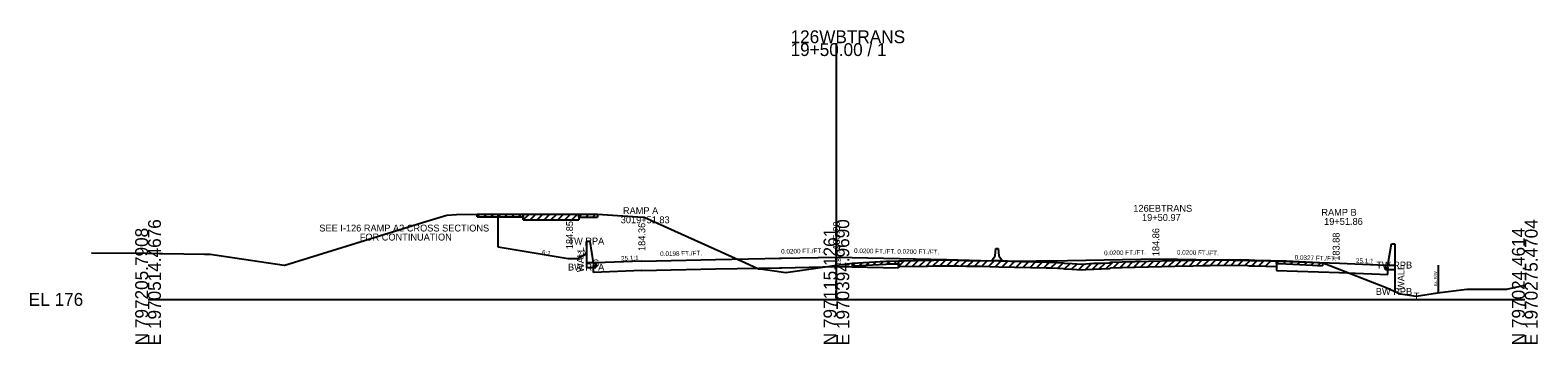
# Model space of a CAD drawing. Extents: x -6494 to 1970605, y -10 to 798140.
# Drawn here: x 974.3 to 1302.8, y 1990.3 to 2058.7 of the extents above; entities that cross this region are included whole.
import ezdxf

# ---------------------------------------------------------------- set-up
doc = ezdxf.new("R2010")
doc.units = 0
for name, color, linetype in [('Default', 7, 'Continuous'), ('RD_EX_SU_Misc_TxCode', 7, 'Continuous'), ('RD_GPK_XS_Cell', 7, 'Continuous'), ('RD_Sketch1', 7, 'Continuous'), ('RD_XS_Base', 7, 'Continuous'), ('RD_XS_Box', 7, 'Continuous'), ('RD_XS_EwShp', 7, 'Continuous'), ('RD_XS_ExGround', 7, 'Continuous'), ('RD_XS_ExPaveRet', 7, 'Continuous'), ('RD_XS_ExRW', 7, 'Continuous'), ('RD_XS_MedBWall', 7, 'Continuous'), ('RD_XS_Misc_Line', 7, 'Continuous'), ('RD_XS_Pave', 7, 'Continuous'), ('RD_XS_PaveOvlay', 7, 'Continuous'), ('RD_XS_PaveShd', 7, 'Continuous'), ('RD_XS_TieSlope', 7, 'Continuous'), ('RD_XS_TX_Elev_EX', 7, 'Continuous'), ('RD_XS_TX_Elev_PR', 7, 'Continuous'), ('RD_XS_TX_Misc', 7, 'Continuous'), ('RD_XS_TX_Notes', 7, 'Continuous'), ('RD_XS_TX_Profile', 7, 'Continuous'), ('RD_XS_TX_Slope', 7, 'Continuous'), ('RD_XS_TX_Station', 7, 'Continuous')]:
    doc.layers.add(name, color=color, linetype=linetype)

msp = doc.modelspace()

# ---------------------------------------------------------------- linework, layer by layer
at = {"layer": 'Default'}
for p, q in [((1184.58, 2009.5), (1184.75, 2011.08)), ((1184.75, 2011.08), (1185.25, 2011.08)), ((1185.25, 2011.08), (1185.42, 2009.5)), ((1184, 2008.67), (1184.58, 2009.5)), ((1184, 2008.42), (1184, 2008.67)), ((1186, 2008.42), (1184, 2008.42)), ((1185.42, 2009.5), (1186, 2008.67)), ((1186, 2008.67), (1186, 2008.42))]:
    msp.add_line(p, q, dxfattribs=at)
at = {"layer": 'RD_GPK_XS_Cell'}
for p, q in [((1150, 2000), (1150, 2055.87)), ((1000, 2000), (1150, 2000)), ((1150, 2000), (1300, 2000))]:
    msp.add_line(p, q, dxfattribs=at)
at = {"layer": 'RD_XS_Base'}
for p, q in [((1097.06, 2007.38), (1097.56, 2007.4)), ((1097.06, 2005.9), (1097.06, 2007.38)), ((1097.56, 2007.4), (1097.56, 2007.96)), ((1269.67, 2006.92), (1269.67, 2007.48)), ((1107.59, 2006.32), (1097.06, 2005.9)), ((1107.59, 2006.32), (1123.63, 2006.64)), ((1123.63, 2006.64), (1137.79, 2006.92)), ((1137.59, 2006.92), (1138, 2006.92)), ((1138, 2006.92), (1150, 2007.16)), ((1150, 2007.16), (1163.49, 2006.89)), ((1245.9, 2006.3), (1259.63, 2005.84)), ((1259.63, 2005.84), (1270.17, 2005.42)), ((1270.17, 2006.9), (1269.67, 2006.92)), ((1270.17, 2005.42), (1270.17, 2006.9))]:
    msp.add_line(p, q, dxfattribs=at)
at = {"layer": 'RD_XS_Box'}
for p, q in [((1095.56, 2011.8), (1095.56, 2007.96)), ((1097.56, 2007.96), (1095.56, 2007.96)), ((1269.67, 2007.48), (1271.68, 2007.48)), ((1271.68, 2007.48), (1271.68, 2001.74))]:
    msp.add_line(p, q, dxfattribs=at)
at = {"layer": 'RD_XS_ExGround'}
msp.add_line((987.67, 2010.15), (1000, 2010.05), dxfattribs=at)
msp.add_lwpolyline([(1000, 2010.05), (1002.48, 2010.03), (1003.14, 2010.03), (1007.8, 2009.94), (1012.29, 2009.86), (1013.51, 2009.84), (1029.68, 2007.49), (1029.83, 2007.48), (1060.74, 2017.07), (1065.09, 2018.4), (1067.21, 2018.48), (1071.69, 2018.62), (1074.17, 2018.62), (1077.48, 2018.62), (1084.94, 2018.6), (1094.44, 2018.59), (1096.53, 2018.58), (1097.91, 2018.57), (1107.79, 2017.95), (1108.09, 2017.93), (1130.07, 2008.04), (1133.01, 2006.7), (1133.93, 2006.58), (1135.5, 2006.36), (1138.95, 2005.88), (1147.07, 2007.04), (1150, 2007.44), (1153.49, 2007.91), (1160.76, 2008.34), (1161.26, 2008.37), (1161.76, 2008.37), (1169.83, 2008.53), (1171.19, 2008.55), (1173.61, 2008.6), (1176.58, 2008.55), (1178.37, 2008.52), (1181.39, 2008.47), (1185.4, 2008.39), (1195.68, 2008.15), (1196.93, 2008.12), (1199.43, 2008), (1199.7, 2007.9), (1201.33, 2007.81), (1203.39, 2007.68), (1204.36, 2007.77), (1206.07, 2007.88), (1207.66, 2007.92), (1209.56, 2008.01), (1209.76, 2008.13), (1212.23, 2008.22), (1223.73, 2008.5), (1227.76, 2008.59), (1229.72, 2008.62), (1231.43, 2008.66), (1235.71, 2008.72), (1239.58, 2008.61), (1239.91, 2008.6), (1241.2, 2008.56), (1247.97, 2008.39), (1253.72, 2008.09), (1255.9, 2007.97), (1257.51, 2007.38), (1269.79, 2002.57), (1272.81, 2001.23), (1273.93, 2001.08), (1276.36, 2000.71), (1280.98, 2001.45), (1287.37, 2002.21), (1294.36, 2002.27), (1296.07, 2002.25), (1299.67, 2003.06), (1300, 2003.14)], dxfattribs=at)
at = {"layer": 'RD_XS_ExPaveRet'}
for p, q in [((1071.69, 2017.99), (1071.69, 2018.62)), ((1071.69, 2017.99), (1074.17, 2018)), ((1074.17, 2018), (1077.48, 2018)), ((1077.48, 2018), (1081.75, 2017.98)), ((1081.75, 2017.36), (1081.75, 2018.61)), ((1081.75, 2018.61), (1081.75, 2017.98)), ((1081.75, 2017.36), (1084.94, 2017.35)), ((1084.94, 2017.35), (1093.89, 2017.34)), ((1093.89, 2018.59), (1093.89, 2017.34)), ((1093.89, 2017.96), (1093.89, 2018.59)), ((1093.89, 2017.96), (1094.44, 2017.96)), ((1094.44, 2017.96), (1096.53, 2017.95)), ((1096.53, 2017.95), (1097.91, 2017.95)), ((1097.91, 2018.57), (1097.91, 2017.95)), ((1153.49, 2007.29), (1153.49, 2007.91)), ((1153.49, 2007.29), (1160.76, 2007.71)), ((1160.76, 2007.71), (1161.26, 2007.74)), ((1161.26, 2007.74), (1161.76, 2007.75)), ((1161.76, 2007.75), (1163.49, 2007.78)), ((1163.49, 2007.16), (1163.49, 2008.41)), ((1163.49, 2008.41), (1163.49, 2007.78)), ((1171.19, 2007.3), (1173.61, 2007.35)), ((1173.61, 2007.35), (1176.58, 2007.3)), ((1223.73, 2007.25), (1227.76, 2007.34)), ((1227.76, 2007.34), (1229.72, 2007.37)), ((1229.72, 2007.37), (1231.43, 2007.41)), ((1231.43, 2007.41), (1235.71, 2007.47)), ((1235.71, 2007.47), (1239.58, 2007.36)), ((1239.58, 2007.36), (1239.91, 2007.35)), ((1239.91, 2007.35), (1241.2, 2007.31)), ((1245.9, 2008.44), (1245.9, 2007.19)), ((1245.9, 2007.82), (1245.9, 2008.44)), ((1245.9, 2007.82), (1247.97, 2007.76)), ((1247.97, 2007.76), (1253.72, 2007.46)), ((1253.72, 2007.46), (1255.9, 2007.35)), ((1255.9, 2007.97), (1255.9, 2007.35)), ((1163.49, 2007.16), (1169.83, 2007.28)), ((1169.83, 2007.28), (1171.19, 2007.3)), ((1176.58, 2007.3), (1178.37, 2007.27)), ((1178.37, 2007.27), (1181.39, 2007.22)), ((1181.39, 2007.22), (1185.4, 2007.14)), ((1185.4, 2007.14), (1195.68, 2006.9)), ((1195.68, 2006.9), (1196.93, 2006.87)), ((1196.93, 2006.87), (1199.43, 2006.75)), ((1199.43, 2006.75), (1199.7, 2006.65)), ((1199.7, 2006.65), (1201.33, 2006.56)), ((1201.33, 2006.56), (1203.39, 2006.43)), ((1203.39, 2006.43), (1204.36, 2006.52)), ((1204.36, 2006.52), (1206.07, 2006.63)), ((1206.07, 2006.63), (1207.66, 2006.67)), ((1207.66, 2006.67), (1209.56, 2006.76)), ((1209.56, 2006.76), (1209.76, 2006.88)), ((1209.76, 2006.88), (1212.23, 2006.97)), ((1212.23, 2006.97), (1223.73, 2007.25)), ((1241.2, 2007.31), (1245.9, 2007.19))]:
    msp.add_line(p, q, dxfattribs=at)
at = {"layer": 'RD_XS_ExRW'}
msp.add_line((1281.1, 2007.46), (1281.1, 2001.46), dxfattribs=at)
at = {"layer": 'RD_XS_MedBWall'}
for p, q in [((1095.56, 2011.71), (1095.56, 2012.63)), ((1096.31, 2012.63), (1095.56, 2012.63)), ((1095.56, 2012.63), (1095.56, 2006.96)), ((1097.06, 2007.96), (1096.31, 2012.63)), ((1270.17, 2007.48), (1270.92, 2012.15)), ((1270.92, 2012.15), (1271.67, 2012.15)), ((1271.67, 2012.15), (1271.67, 2006.48)), ((1097.56, 2007.96), (1097.06, 2007.96)), ((1097.56, 2006.96), (1097.56, 2007.96)), ((1269.67, 2006.48), (1269.67, 2007.48)), ((1269.67, 2007.48), (1270.17, 2007.48)), ((1095.56, 2006.96), (1097.56, 2006.96)), ((1271.67, 2006.48), (1269.67, 2006.48))]:
    msp.add_line(p, q, dxfattribs=at)
at = {"layer": 'RD_XS_Misc_Line'}
for p, q in [((1071.69, 2017.99), (1072.32, 2018.62)), ((1073.2, 2018), (1073.83, 2018.62)), ((1074.71, 2018), (1075.34, 2018.62)), ((1076.22, 2018), (1076.85, 2018.62)), ((1077.73, 2018), (1078.35, 2018.62)), ((1079.24, 2017.99), (1079.86, 2018.62)), ((1080.75, 2017.99), (1081.37, 2018.61)), ((1081.75, 2017.36), (1083.01, 2018.6)), ((1083.26, 2017.35), (1084.52, 2018.6)), ((1084.77, 2017.35), (1086.03, 2018.6)), ((1086.28, 2017.35), (1087.54, 2018.59)), ((1087.79, 2017.34), (1089.05, 2018.59)), ((1089.3, 2017.34), (1090.56, 2018.59)), ((1090.81, 2017.34), (1092.07, 2018.59)), ((1092.32, 2017.34), (1093.58, 2018.59)), ((1093.89, 2017.96), (1094.51, 2018.59)), ((1095.4, 2017.96), (1096.02, 2018.58)), ((1096.91, 2017.95), (1097.53, 2018.57)), ((1153.49, 2007.29), (1154.16, 2007.95)), ((1155, 2007.37), (1155.67, 2008.04)), ((1156.51, 2007.46), (1157.18, 2008.13)), ((1158.02, 2007.55), (1158.69, 2008.21)), ((1159.53, 2007.64), (1160.2, 2008.3)), ((1161.04, 2007.73), (1161.69, 2008.37)), ((1162.55, 2007.76), (1163.19, 2008.4)), ((1163.49, 2007.16), (1164.77, 2008.43)), ((1165, 2007.19), (1166.28, 2008.46)), ((1166.51, 2007.21), (1167.79, 2008.49)), ((1168.02, 2007.24), (1169.3, 2008.52)), ((1169.53, 2007.27), (1170.81, 2008.54)), ((1171.04, 2007.3), (1172.33, 2008.57)), ((1172.55, 2007.33), (1173.83, 2008.6)), ((1174.06, 2007.35), (1175.3, 2008.57)), ((1175.57, 2007.32), (1176.81, 2008.55)), ((1177.08, 2007.29), (1178.32, 2008.52)), ((1178.59, 2007.27), (1179.83, 2008.49)), ((1180.1, 2007.24), (1181.34, 2008.47)), ((1181.61, 2007.21), (1182.85, 2008.44)), ((1183.12, 2007.18), (1184.36, 2008.41)), ((1184.63, 2007.15), (1185.86, 2008.38)), ((1186.14, 2007.12), (1187.37, 2008.34)), ((1187.65, 2007.09), (1188.88, 2008.31)), ((1189.16, 2007.05), (1190.39, 2008.27)), ((1190.67, 2007.01), (1191.9, 2008.24)), ((1192.18, 2006.98), (1193.41, 2008.2)), ((1193.69, 2006.94), (1194.92, 2008.16)), ((1195.2, 2006.91), (1196.43, 2008.13)), ((1196.71, 2006.87), (1197.92, 2008.07)), ((1198.22, 2006.81), (1199.42, 2008)), ((1199.73, 2006.64), (1200.93, 2007.83)), ((1201.24, 2006.56), (1202.43, 2007.74)), ((1202.75, 2006.47), (1204.03, 2007.74)), ((1204.26, 2006.51), (1205.61, 2007.85)), ((1205.77, 2006.61), (1207.08, 2007.9)), ((1207.28, 2006.66), (1208.6, 2007.96)), ((1208.79, 2006.72), (1210.23, 2008.14)), ((1210.3, 2006.9), (1211.61, 2008.2)), ((1211.81, 2006.95), (1213.11, 2008.24)), ((1213.32, 2006.99), (1214.61, 2008.28)), ((1214.83, 2007.03), (1216.12, 2008.31)), ((1216.34, 2007.07), (1217.63, 2008.35)), ((1217.85, 2007.11), (1219.14, 2008.39)), ((1219.36, 2007.14), (1220.65, 2008.42)), ((1220.87, 2007.18), (1222.16, 2008.46)), ((1222.38, 2007.22), (1223.67, 2008.5)), ((1223.89, 2007.25), (1225.18, 2008.53)), ((1225.4, 2007.29), (1226.69, 2008.57)), ((1226.91, 2007.32), (1228.2, 2008.6)), ((1228.42, 2007.35), (1229.71, 2008.62)), ((1229.93, 2007.38), (1231.22, 2008.65)), ((1231.44, 2007.41), (1232.72, 2008.68)), ((1232.95, 2007.43), (1234.23, 2008.7)), ((1234.47, 2007.45), (1235.74, 2008.72)), ((1235.98, 2007.46), (1237.2, 2008.68)), ((1237.49, 2007.42), (1238.71, 2008.63)), ((1239, 2007.37), (1240.22, 2008.59)), ((1240.51, 2007.33), (1241.73, 2008.55)), ((1242.02, 2007.29), (1243.24, 2008.51)), ((1243.53, 2007.25), (1244.75, 2008.47)), ((1245.9, 2007.82), (1246.51, 2008.43)), ((1247.41, 2007.78), (1248.02, 2008.38)), ((1248.92, 2007.71), (1249.52, 2008.31)), ((1250.43, 2007.63), (1251.03, 2008.23)), ((1251.94, 2007.56), (1252.54, 2008.15)), ((1253.45, 2007.48), (1254.05, 2008.07)), ((1254.96, 2007.4), (1255.56, 2007.99))]:
    msp.add_line(p, q, dxfattribs=at)
at = {"layer": 'RD_XS_Pave'}
for p, q in [((1107.59, 2008.36), (1123.63, 2008.68)), ((1137.59, 2008.96), (1138, 2008.96)), ((1138, 2008.96), (1150, 2009.2)), ((1150, 2009.2), (1174, 2008.72)), ((1196.35, 2008.38), (1220.35, 2008.86)), ((1220.35, 2008.86), (1232.35, 2008.62)), ((1232.35, 2008.62), (1244.35, 2008.38)), ((1244.35, 2008.38), (1259.63, 2007.88))]:
    msp.add_line(p, q, dxfattribs=at)
at = {"layer": 'RD_XS_PaveOvlay'}
for p, q in [((1163.49, 2008.41), (1169.83, 2008.53)), ((1163.49, 2008.41), (1163.49, 2006.89)), ((1169.83, 2008.53), (1171.19, 2008.55)), ((1171.19, 2008.55), (1173.61, 2008.6)), ((1173.61, 2008.6), (1176.58, 2008.55)), ((1176.58, 2008.55), (1178.37, 2008.52)), ((1178.37, 2008.52), (1181.39, 2008.47)), ((1181.39, 2008.47), (1185.4, 2008.39)), ((1185.4, 2008.39), (1195.68, 2008.15)), ((1195.68, 2008.15), (1196.93, 2008.12)), ((1196.93, 2008.12), (1199.43, 2008)), ((1199.43, 2008), (1199.7, 2007.9)), ((1199.7, 2007.9), (1201.33, 2007.81)), ((1201.33, 2007.81), (1203.39, 2007.68)), ((1203.39, 2007.68), (1204.36, 2007.77)), ((1204.36, 2007.77), (1206.07, 2007.88)), ((1206.07, 2007.88), (1207.66, 2007.92)), ((1207.66, 2007.92), (1209.56, 2008.01)), ((1209.56, 2008.01), (1209.76, 2008.13)), ((1209.76, 2008.13), (1212.23, 2008.22)), ((1212.23, 2008.22), (1223.73, 2008.5)), ((1223.73, 2008.5), (1227.76, 2008.59)), ((1227.76, 2008.59), (1229.72, 2008.62)), ((1229.72, 2008.62), (1231.43, 2008.66)), ((1231.43, 2008.66), (1235.71, 2008.72)), ((1235.71, 2008.72), (1239.58, 2008.61)), ((1239.58, 2008.61), (1239.91, 2008.6)), ((1239.91, 2008.6), (1241.2, 2008.56)), ((1241.2, 2008.56), (1245.9, 2008.44)), ((1245.9, 2008.44), (1245.9, 2006.3))]:
    msp.add_line(p, q, dxfattribs=at)
at = {"layer": 'RD_XS_PaveShd'}
for p, q in [((1107.59, 2008.36), (1097.56, 2007.96)), ((1123.63, 2008.68), (1138, 2008.96)), ((1174, 2008.72), (1184, 2008.42)), ((1190.61, 2008.27), (1184, 2008.42)), ((1196.35, 2008.38), (1190.61, 2008.27)), ((1259.63, 2007.88), (1269.67, 2007.48))]:
    msp.add_line(p, q, dxfattribs=at)
at = {"layer": 'RD_XS_TieSlope'}
for p, q in [((1076.32, 2011.39), (1076.32, 2018.62)), ((1091.56, 2008.85), (1076.32, 2011.39)), ((1093.56, 2008.85), (1091.56, 2008.85)), ((1095.56, 2009.85), (1093.56, 2008.85))]:
    msp.add_line(p, q, dxfattribs=at)

# ---------------------------------------------------------------- texts
at = {"layer": 'RD_EX_SU_Misc_TxCode'}
msp.add_text('G', height=1.5, dxfattribs=at).set_placement((1096.81, 2007.21))
at = {"layer": 'RD_GPK_XS_Cell'}
for s, p in [('126WBTRANS', (1140, 2055.87)), ('19+50.00 / 1', (1140, 2053.07)), ('EL 176', (974, 1998.6))]:
    msp.add_text(s, height=2.8, dxfattribs=at).set_placement(p)
for s, p in [('E 1970514.4676', (1002.8, 1990)), ('E 1970394.9690', (1152.8, 1990)), ('E 1970275.4704', (1302.8, 1990)), ('N 797205.7908', (1000, 1990)), ('N 797115.1261', (1150, 1990)), ('N 797024.4614', (1300, 1990))]:
    msp.add_text(s, height=2.8, rotation=90, dxfattribs=at).set_placement(p)
at = {"layer": 'RD_Sketch1'}
msp.add_text('T', height=1.5, dxfattribs=at).set_placement((1275.8, 1999.96))
at = {"layer": 'RD_XS_EwShp'}
for s, p in [('TW RPA', (1091.6, 2011.97)), ('BW RPA', (1091.5, 2006.3)), ('TW RPB', (1267.65, 2006.73)), ('BW RPB', (1267.54, 2000.99))]:
    msp.add_text(s, height=1.5, dxfattribs=at).set_placement(p)
at = {"layer": 'RD_XS_ExRW'}
msp.add_text('Ex. R/W ', height=0.65, rotation=90, dxfattribs=at).set_placement((1280.85, 2002.84))
at = {"layer": 'RD_XS_TX_Elev_EX'}
msp.add_text('183.44', height=1, rotation=90, dxfattribs=at).set_placement((1151, 2007.44))
at = {"layer": 'RD_XS_TX_Elev_PR'}
for s, p in [('184.36', (1108.34, 2010.56)), ('185.20', (1150.75, 2010.87)), (' 184.86', (1220.35, 2008.86)), (' 183.88', (1259.63, 2007.88))]:
    msp.add_text(s, height=1.5, rotation=90, dxfattribs=at).set_placement(p)
at = {"layer": 'RD_XS_TX_Misc'}
msp.add_text('184.85', height=1.5, rotation=90, dxfattribs=at).set_placement((1092.6, 2010.95))
at = {"layer": 'RD_XS_TX_Notes'}
for s, p in [('SEE I-126 RAMP A2 CROSS SECTIONS', (1037.32, 2014.81)), ('FOR CONTINUATION', (1046.13, 2012.84))]:
    msp.add_text(s, height=1.5, dxfattribs=at).set_placement(p)
for p in [(1094.99, 2005.95), (1273.77, 2002.05)]:
    msp.add_text('WALL', height=1.5, rotation=90, dxfattribs=at).set_placement(p)
at = {"layer": 'RD_XS_TX_Profile'}
msp.add_text('25.1:1', height=1, rotation=357.7174, dxfattribs=at).set_placement((1263.18, 2007.99))
at = {"layer": 'RD_XS_TX_Slope'}
for s, rotation, p in [('6:1', 350.5377, (1085.76, 2009.82)), ('2:1', 26.5651, (1093.96, 2009.36)), ('0.0198 FT./FT.', 1.1369, (1111.6, 2009.44)), ('0.0200 FT./FT.', 1.1437, (1137.96, 2009.96)), ('0.0200 FT./FT.', 358.8542, (1153.83, 2010.13)), ('0.0200 FT./FT.', 358.8542, (1163.26, 2010)), ('0.0200 FT./FT.', 1.1455, (1208.33, 2009.62)), ('0.0200 FT./FT.', 358.854, (1224.18, 2009.78)), ('25.1:1', 2.285, (1103.09, 2008.43)), ('0.0327 FT./FT.', 358.1253, (1249.84, 2008.68))]:
    msp.add_text(s, height=1, rotation=rotation, dxfattribs=at).set_placement(p)
at = {"layer": 'RD_XS_TX_Station'}
for s, p in [('126EBTRANS', (1214.7, 2019.11)), ('3019+51.83', (1103, 2016.61)), ('RAMP A', (1103.48, 2018.61)), ('19+50.97', (1216.59, 2017.11)), ('RAMP B', (1255.67, 2018.25)), ('19+51.86', (1256.27, 2016.25))]:
    msp.add_text(s, height=1.5, dxfattribs=at).set_placement(p)

doc.saveas('drawing.dxf')
